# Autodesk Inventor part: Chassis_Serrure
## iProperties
Created: 2009-01
Part Number: Chassis_Serrure
Document SubType Name: Sheet Metal
Designer: claivier
Author: claivier
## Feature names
1. Chanfrein de coin1
2. Perçage1 [Hole]
3. Plaque1
4. Pli1
5. Couper1
